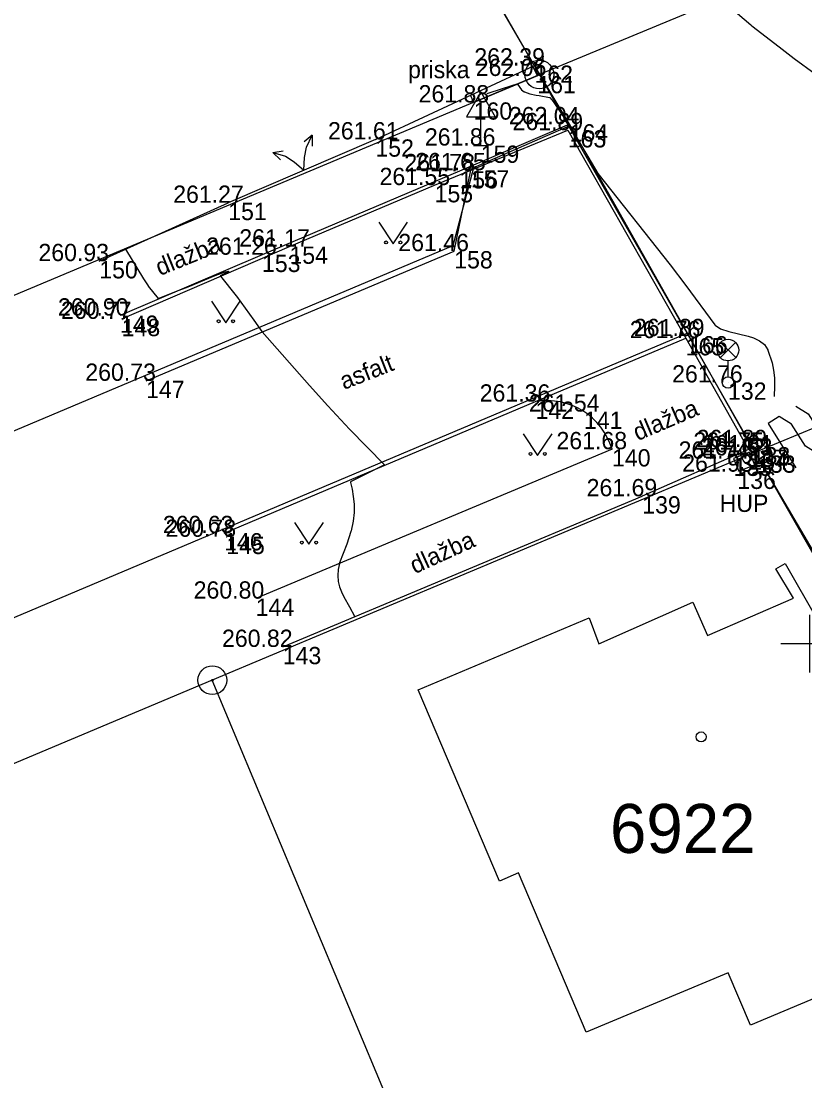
# Model space of a CAD drawing. Extents: x -771260 to -770828, y -1053564 to -1052811.
# Drawn here: x -771177.41 to -771150.16, y -1053315.19 to -1053278.38 of the extents above; entities that cross this region are included whole.
import ezdxf

# ---------------------------------------------------------------- set-up
doc = ezdxf.new("R2010")
doc.units = 0
for name, color, linetype in [('14_8_2023_krizky', 7, 'Continuous'), ('25_3_2019_dopravni_znacka', 7, 'Continuous'), ('25_3_2019_HUP', 7, 'Continuous'), ('25_3_2019_krizky_JTSK', 7, 'Continuous'), ('25_3_2019_lampa', 7, 'Continuous'), ('25_3_2019_obrubnik', 7, 'Continuous'), ('25_3_2019_oploceni', 7, 'Continuous'), ('25_3_2019_popis_objektu', 7, 'Continuous'), ('25_3_2019_popis_povrchu', 7, 'Continuous'), ('25_3_2019_priska', 7, 'Continuous'), ('25_3_2019_vrstevnice_interval_po_1m', 7, 'Continuous'), ('25_3_2019_vstup_vjezd_pozemek', 7, 'Continuous'), ('25_3_2019_zamereny_bod', 7, 'Continuous'), ('25_3_2019_zamereny_bod_cislo', 7, 'Continuous'), ('25_3_2019_zamereny_bod_vyska', 7, 'Continuous'), ('25_3_2019_znacka_zelen', 7, 'Continuous'), ('Default', 7, 'Continuous'), ('DKM_Hranice parcel', 7, 'Continuous'), ('DKM_Parcelní čísla', 7, 'Continuous'), ('DKM_Značky bodu BP', 7, 'Continuous'), ('DKM_Značky budov', 7, 'Continuous')]:
    doc.layers.add(name, color=color, linetype=linetype)

# ---------------------------------------------------------------- blocks, each defined once
blk = doc.blocks.new('Z58')
at = {"layer": '25_3_2019_vstup_vjezd_pozemek'}
for p, q in [((-7.5, 10), (-4, 7)), ((-7.5, 10), (-6, 6.51)), ((-7.5, 10), (-4, 9.01)), ((4, 7.01), (7.5, 10)), ((7.5, 10), (4, 9)), ((7.5, 10), (6, 6.5)), ((-4, 7), (-1.99, 4)), ((-1.99, 4), (0, 0)), ((0, 0), (2, 4)), ((2, 4), (4, 7.01))]:
    blk.add_line(p, q, dxfattribs=at)
blk = doc.blocks.new('5.270_1')
at = {"layer": '25_3_2019_dopravni_znacka'}
for p, q in [((0, 37.32), (-10, 20)), ((0, 37.32), (10, 20)), ((-10, 20), (10, 20)), ((0, 0), (0, 20)), ((-5, 0), (5, 0))]:
    blk.add_line(p, q, dxfattribs=at)
blk = doc.blocks.new('6.560_1')
at = {"layer": '25_3_2019_lampa'}
for p, q in [((-5.28, 17.24), (5.28, 27.8)), ((5.44, 17.3), (-5.12, 27.88)), ((0, 4), (0, 15))]:
    blk.add_line(p, q, dxfattribs=at)
for centre, radius in [((0, 22.5), 7.5), ((0, 0), 4), ((0, 0), 4)]:
    blk.add_circle(centre, radius, dxfattribs=at)
blk = doc.blocks.new('3.140_1')
at = {"layer": '25_3_2019_znacka_zelen'}
blk.add_lwpolyline([(-10, 15), (0, 0), (10, 15)], dxfattribs=at)
for centre in [(-5, 1), (-5, 1), (5, 1), (5, 1)]:
    blk.add_circle(centre, 1, dxfattribs=at)
blk = doc.blocks.new('POINT_DISPLAY')
at = {"layer": 'Default'}
blk.add_line((0, 0), (0, 0), dxfattribs=at)
blk = doc.blocks.new('KRIZEK')
at = {"layer": '25_3_2019_krizky_JTSK'}
for p, q in [((0, 10), (0, -10)), ((-10, 0), (10, 0))]:
    blk.add_line(p, q, dxfattribs=at)

msp = doc.modelspace()

# ---------------------------------------------------------------- linework, layer by layer
at = {"layer": '25_3_2019_HUP'}
for p, q in [((-771152.089, -1053293.353), (-771152.635, -1053293.573)), ((-771152.089, -1053293.353), (-771151.914, -1053293.786)), ((-771152.635, -1053293.573), (-771152.459, -1053294.007)), ((-771152.459, -1053294.007), (-771151.914, -1053293.786))]:
    msp.add_line(p, q, dxfattribs=at)
at = {"layer": '25_3_2019_obrubnik'}
for p, q in [((-771158.337, -1053281.957), (-771159.56, -1053279.916)), ((-771158.337, -1053281.957), (-771162.167, -1053283.587)), ((-771161.774, -1053283.553), (-771158.403, -1053282.162)), ((-771158.403, -1053282.162), (-771154.301, -1053289.385)), ((-771154.183, -1053289.316), (-771158.337, -1053281.957)), ((-771162.167, -1053283.587), (-771169.032, -1053286.491)), ((-771163.03, -1053284.07), (-771161.774, -1053283.553)), ((-771162.35, -1053286.365), (-771161.774, -1053283.553)), ((-771168.08, -1053286.204), (-771163.03, -1053284.07)), ((-771173.909, -1053288.719), (-771168.08, -1053286.204)), ((-771169.032, -1053286.491), (-771173.967, -1053288.602)), ((-771173.063, -1053290.868), (-771162.35, -1053286.365)), ((-771159.521, -1053291.591), (-771154.301, -1053289.385)), ((-771154.301, -1053289.385), (-771152.119, -1053293.257)), ((-771152.006, -1053293.172), (-771154.183, -1053289.316)), ((-771170.35, -1053296.16), (-771159.521, -1053291.591)), ((-771156.863, -1053293.244), (-771169.251, -1053298.435)), ((-771152.119, -1053293.257), (-771155.812, -1053294.879)), ((-771168.31, -1053300.113), (-771155.812, -1053294.879))]:
    msp.add_line(p, q, dxfattribs=at)
msp.add_arc((-771159.125, -1053293.917), 2.359, 16.5635, 99.6785, dxfattribs=at)
at = {"layer": '25_3_2019_oploceni'}
for p, q in [((-771159.56, -1053279.916), (-771167.412, -1053266.462)), ((-771165.09, -1053282.483), (-771159.56, -1053279.917)), ((-771174.69, -1053286.712), (-771170.207, -1053284.687)), ((-771147.237, -1053301.266), (-771151.821, -1053293.463))]:
    msp.add_line(p, q, dxfattribs=at)
at = {"layer": '25_3_2019_priska'}
for p, q in [((-771159.459, -1053280.28), (-771159.616, -1053279.943)), ((-771159.459, -1053280.28), (-771161.674, -1053281.197)), ((-771161.674, -1053281.197), (-771161.788, -1053280.951))]:
    msp.add_line(p, q, dxfattribs=at)
at = {"layer": '25_3_2019_vrstevnice_interval_po_1m'}
for points in [[(-771153.199, -1053277.504), (-771152.035, -1053278.507), (-771151.999, -1053278.538), (-771151.054, -1053279.264), (-771150.533, -1053279.674), (-771149.799, -1053280.202), (-771149.134, -1053280.696), (-771148.539, -1053281.114), (-771147.912, -1053281.584)], [(-771151.999, -1053278.538), (-771151.999, -1053278.538)], [(-771151.054, -1053279.264), (-771151.054, -1053279.264)], [(-771150.533, -1053279.674), (-771150.533, -1053279.674)], [(-771161.202, -1053280.893), (-771161.134, -1053280.871), (-771160.346, -1053280.607), (-771160.166, -1053280.554), (-771160.155, -1053280.569), (-771160.013, -1053280.764), (-771159.92, -1053280.831), (-771159.911, -1053280.835), (-771159.718, -1053280.901), (-771159.496, -1053280.946), (-771159.396, -1053280.957), (-771159.043, -1053281.023), (-771159.024, -1053281.027), (-771158.915, -1053281.164), (-771158.35, -1053281.99), (-771158.349, -1053281.992), (-771157.708, -1053283.073), (-771157.355, -1053283.669), (-771154.843, -1053286.846), (-771154.3, -1053287.553), (-771153.292, -1053288.928), (-771153.274, -1053288.94), (-771153.095, -1053289.064), (-771152.805, -1053289.16), (-771152.136, -1053289.318), (-771151.946, -1053289.378), (-771151.732, -1053289.475), (-771151.562, -1053289.608), (-771151.452, -1053289.79), (-771151.447, -1053289.803), (-771151.297, -1053290.247), (-771151.247, -1053290.498), (-771151.219, -1053290.767), (-771151.212, -1053291.052), (-771151.223, -1053291.412)], [(-771160.346, -1053280.607), (-771160.346, -1053280.607)], [(-771160.166, -1053280.554), (-771160.166, -1053280.554)], [(-771160.013, -1053280.764), (-771160.013, -1053280.764)], [(-771159.92, -1053280.831), (-771159.92, -1053280.831)], [(-771161.202, -1053280.893), (-771161.202, -1053280.893)], [(-771159.718, -1053280.901), (-771159.718, -1053280.901)], [(-771159.496, -1053280.946), (-771159.496, -1053280.946)], [(-771159.396, -1053280.957), (-771159.396, -1053280.957)], [(-771159.024, -1053281.027), (-771159.024, -1053281.027)], [(-771158.915, -1053281.164), (-771158.915, -1053281.164)], [(-771158.35, -1053281.99), (-771158.35, -1053281.99)], [(-771157.355, -1053283.669), (-771157.355, -1053283.669)], [(-771173.792, -1053286.287), (-771173.792, -1053286.287)], [(-771173.792, -1053286.287), (-771173.783, -1053286.302), (-771173.155, -1053287.329), (-771172.992, -1053287.569), (-771172.985, -1053287.578), (-771172.64, -1053288.015), (-771172.001, -1053287.761), (-771171.596, -1053287.6), (-771170.663, -1053287.216), (-771170.437, -1053287.132), (-771170.312, -1053287.086), (-771170.196, -1053287.063), (-771170.191, -1053287.071), (-771170.486, -1053287.223), (-771170.474, -1053287.237), (-771169.928, -1053287.918), (-771169.921, -1053287.928), (-771169.313, -1053288.759), (-771169.035, -1053289.156), (-771169.023, -1053289.17), (-771167.378, -1053291.032), (-771166.749, -1053291.734), (-771166.742, -1053291.742), (-771165.992, -1053292.546), (-771164.77, -1053293.786), (-771165.008, -1053293.906), (-771165.957, -1053294.383), (-771165.953, -1053294.401), (-771165.902, -1053294.629), (-771165.858, -1053294.884), (-771165.833, -1053295.153), (-771165.833, -1053295.44), (-771165.864, -1053295.749), (-771165.933, -1053296.083), (-771165.94, -1053296.107), (-771166.08, -1053296.539), (-771166.338, -1053297.196), (-771166.343, -1053297.218), (-771166.39, -1053297.425), (-771166.402, -1053297.637), (-771166.381, -1053297.835), (-771166.335, -1053298.023), (-771166.268, -1053298.202), (-771166.188, -1053298.375), (-771165.994, -1053298.723), (-771165.813, -1053299.048)], [(-771170.312, -1053287.086), (-771170.312, -1053287.086)], [(-771170.196, -1053287.063), (-771170.196, -1053287.063)], [(-771170.191, -1053287.071), (-771170.191, -1053287.071)], [(-771154.843, -1053286.846), (-771154.843, -1053286.846)], [(-771173.155, -1053287.329), (-771173.155, -1053287.329)], [(-771170.663, -1053287.216), (-771170.663, -1053287.216)], [(-771170.486, -1053287.223), (-771170.486, -1053287.223)], [(-771172.992, -1053287.569), (-771172.992, -1053287.569)], [(-771171.596, -1053287.6), (-771171.596, -1053287.6)], [(-771154.3, -1053287.553), (-771154.3, -1053287.553)], [(-771172.64, -1053288.015), (-771172.64, -1053288.015)], [(-771169.928, -1053287.918), (-771169.928, -1053287.918)], [(-771169.313, -1053288.759), (-771169.313, -1053288.759)], [(-771153.292, -1053288.928), (-771153.292, -1053288.928)], [(-771169.035, -1053289.156), (-771169.035, -1053289.156)], [(-771153.095, -1053289.064), (-771153.095, -1053289.064)], [(-771152.805, -1053289.16), (-771152.805, -1053289.16)], [(-771152.136, -1053289.318), (-771152.136, -1053289.318)], [(-771151.946, -1053289.378), (-771151.946, -1053289.378)], [(-771151.732, -1053289.475), (-771151.732, -1053289.475)], [(-771151.562, -1053289.608), (-771151.562, -1053289.608)], [(-771151.452, -1053289.79), (-771151.452, -1053289.79)], [(-771151.297, -1053290.247), (-771151.297, -1053290.247)], [(-771151.247, -1053290.498), (-771151.247, -1053290.498)], [(-771151.219, -1053290.767), (-771151.219, -1053290.767)], [(-771167.378, -1053291.032), (-771167.378, -1053291.032)], [(-771151.212, -1053291.052), (-771151.212, -1053291.052)], [(-771166.749, -1053291.734), (-771166.749, -1053291.734)], [(-771150.477, -1053291.749), (-771150.044, -1053292.013), (-771149.563, -1053292.783), (-771149.515, -1053293.288), (-771149.708, -1053293.408), (-771150.141, -1053293.144), (-771150.622, -1053292.374), (-771151.055, -1053292.109), (-771151.44, -1053292.35), (-771150.477, -1053293.89)], [(-771165.992, -1053292.546), (-771165.992, -1053292.546)], [(-771164.77, -1053293.786), (-771164.77, -1053293.786)], [(-771165.957, -1053294.383), (-771165.957, -1053294.383)], [(-771165.902, -1053294.629), (-771165.902, -1053294.629)], [(-771165.858, -1053294.884), (-771165.858, -1053294.884)], [(-771165.833, -1053295.153), (-771165.833, -1053295.153)], [(-771165.833, -1053295.44), (-771165.833, -1053295.44)], [(-771165.864, -1053295.749), (-771165.864, -1053295.749)], [(-771165.933, -1053296.083), (-771165.933, -1053296.083)], [(-771166.08, -1053296.539), (-771166.08, -1053296.539)], [(-771166.338, -1053297.196), (-771166.338, -1053297.196)], [(-771166.402, -1053297.637), (-771166.402, -1053297.637)], [(-771166.39, -1053297.425), (-771166.39, -1053297.425)], [(-771166.381, -1053297.835), (-771166.381, -1053297.835)], [(-771166.335, -1053298.023), (-771166.335, -1053298.023)], [(-771166.268, -1053298.202), (-771166.268, -1053298.202)], [(-771166.188, -1053298.375), (-771166.188, -1053298.375)], [(-771165.813, -1053299.048), (-771165.813, -1053299.048)], [(-771165.813, -1053299.048), (-771165.813, -1053299.048)]]:
    msp.add_lwpolyline(points, dxfattribs=at)
at = {"layer": '25_3_2019_vstup_vjezd_pozemek'}
msp.add_line((-771165.089, -1053282.482), (-771170.207, -1053284.687), dxfattribs=at)
at = {"layer": 'DKM_Hranice parcel'}
for p, q in [((-771159.39, -1053280.23), (-771161.21, -1053277.05)), ((-771182.78, -1053290.05), (-771159.39, -1053280.23)), ((-771158.36, -1053282.02), (-771159.39, -1053280.23)), ((-771154.25, -1053289.21), (-771158.36, -1053282.02)), ((-771151.89, -1053293.35), (-771154.25, -1053289.21)), ((-771151.89, -1053293.35), (-771170.76, -1053301.27)), ((-771170.76, -1053301.27), (-771191.78, -1053310.1)), ((-771157.67, -1053332.55), (-771170.76, -1053301.27))]:
    msp.add_line(p, q, dxfattribs=at)
for points in [[(-771114.64, -1053256.15), (-771110.79, -1053262.31), (-771110, -1053265.61), (-771121.4, -1053267.92), (-771131.13, -1053270.31), (-771140.72, -1053273.18), (-771150.13, -1053276.39), (-771159.39, -1053280.23)], [(-771158.36, -1053282.02), (-771161.68, -1053283.47), (-771162.4, -1053286.18), (-771217.48, -1053309.4), (-771221.52, -1053310.31), (-771225.4, -1053309.44), (-771229.05, -1053306.18), (-771230.58, -1053303.61), (-771236.43, -1053293.1), (-771247.022, -1053275.468)], [(-771151.89, -1053293.35), (-771144.83, -1053290.43), (-771136.15, -1053287.47), (-771127.19, -1053284.79), (-771125.28, -1053284.32)], [(-771052.58, -1053353.51), (-771052.72, -1053353.51), (-771055.78, -1053356.02), (-771073.82, -1053356.52), (-771091.31, -1053358.07), (-771113.44, -1053361.51), (-771130.6, -1053365.46), (-771143.48, -1053368.93), (-771156.62, -1053373.29), (-771169.24, -1053378.06), (-771181.81, -1053383.19), (-771186.16, -1053383.15), (-771190.19, -1053380.88), (-771192.42, -1053377.58), (-771218.46, -1053327.01), (-771219.54, -1053322.62), (-771219.14, -1053320.1), (-771217.59, -1053316.97), (-771214.46, -1053314.62), (-771154.25, -1053289.21)], [(-771134.86, -1053323.01), (-771144.3, -1053306.64), (-771151.89, -1053293.35)], [(-771154.06, -1053298.56), (-771153.54, -1053299.72), (-771150.56, -1053298.42), (-771151.17, -1053297.4), (-771150.85, -1053297.22), (-771144.15, -1053308.91), (-771144.47, -1053309.11), (-771146.17, -1053306.1), (-771149.32, -1053307.36), (-771147.63, -1053311.4), (-771152.05, -1053313.25), (-771152.83, -1053311.43), (-771157.76, -1053313.5), (-771160.11, -1053307.96), (-771160.78, -1053308.25), (-771163.6, -1053301.6), (-771157.66, -1053299.1), (-771157.32, -1053300.01), (-771154.06, -1053298.56)]]:
    msp.add_lwpolyline(points, dxfattribs=at)
at = {"layer": 'DKM_Značky bodu BP'}
for centre, radius in [((-771159.39, -1053280.23), 0.5), ((-771159.39, -1053280.23), 0.0303), ((-771151.89, -1053293.35), 0.5), ((-771151.89, -1053293.35), 0.0303), ((-771170.76, -1053301.27), 0.5), ((-771170.76, -1053301.27), 0.0303)]:
    msp.add_circle(centre, radius, dxfattribs=at)
at = {"layer": 'DKM_Značky budov'}
msp.add_circle((-771153.767, -1053303.239), 0.175, dxfattribs=at)

# ---------------------------------------------------------------- block references
at = {"layer": '14_8_2023_krizky', "xscale": 0.1, "yscale": 0.10000000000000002}
msp.add_blockref('KRIZEK', (-771150, -1053300), dxfattribs=at)
at = {"layer": '25_3_2019_dopravni_znacka', "xscale": 0.05, "yscale": 0.05000000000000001}
msp.add_blockref('5.270_1', (-771161.427, -1053282.697), dxfattribs=at)
at = {"layer": '25_3_2019_lampa', "xscale": 0.05, "yscale": 0.05000000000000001}
msp.add_blockref('6.560_1', (-771152.831, -1053290.927), dxfattribs=at)
at = {"layer": '25_3_2019_vstup_vjezd_pozemek', "xscale": 0.09999945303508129, "yscale": 0.09999945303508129, "rotation": 23.399927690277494}
msp.add_blockref('Z58', (-771167.576, -1053283.554), dxfattribs=at)
at = {"layer": '25_3_2019_zamereny_bod', "xscale": 0.1, "yscale": 0.10000000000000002}
for p in [(-771159.56, -1053279.917), (-771159.46, -1053280.281), (-771161.674, -1053281.198), (-771158.403, -1053282.163), (-771158.338, -1053281.957), (-771165.09, -1053282.483), (-771161.427, -1053282.697), (-771162.168, -1053283.588), (-771161.774, -1053283.553), (-771163.031, -1053284.07), (-771170.207, -1053284.687), (-771168.08, -1053286.205), (-771174.69, -1053286.712), (-771169.033, -1053286.491), (-771162.35, -1053286.365), (-771173.968, -1053288.602), (-771173.91, -1053288.719), (-771154.302, -1053289.386), (-771154.184, -1053289.317), (-771173.063, -1053290.869), (-771152.831, -1053290.927), (-771159.521, -1053291.591), (-771157.838, -1053291.939), (-771156.863, -1053293.245), (-771152.119, -1053293.258), (-771152.09, -1053293.353), (-771152.006, -1053293.172), (-771152.635, -1053293.574), (-771151.821, -1053293.463), (-771152.506, -1053294.026), (-771155.812, -1053294.88), (-771170.351, -1053296.16), (-771170.274, -1053296.289), (-771169.251, -1053298.436), (-771168.311, -1053300.113)]:
    msp.add_blockref('POINT_DISPLAY', p, dxfattribs=at)
at = {"layer": '25_3_2019_znacka_zelen', "xscale": 0.05, "yscale": 0.05000000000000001}
for p in [(-771164.47, -1053286.11), (-771170.29, -1053288.85), (-771159.45, -1053293.46), (-771167.4, -1053296.54)]:
    msp.add_blockref('3.140_1', p, dxfattribs=at)

# ---------------------------------------------------------------- texts
at = {"layer": '25_3_2019_popis_objektu'}
for s, p in [('priska', (-771163.955, -1053280.358)), ('HUP', (-771153.121, -1053295.424))]:
    msp.add_text(s, height=0.6, dxfattribs=at).set_placement(p)
at = {"layer": '25_3_2019_popis_povrchu'}
for s, rotation, p in [('dlažba', 21.8897, (-771172.586, -1053287.232)), ('asfalt', 21.4525, (-771166.183, -1053291.187)), ('dlažba', 23.097, (-771155.975, -1053292.967)), ('dlažba', 24.5471, (-771163.72, -1053297.588))]:
    msp.add_text(s, height=0.6, rotation=rotation, dxfattribs=at).set_placement(p)
at = {"layer": '25_3_2019_zamereny_bod_cislo'}
for s, p in [('162', (-771159.56, -1053280.517)), ('161', (-771159.46, -1053280.881)), ('160', (-771161.674, -1053281.798)), ('163', (-771158.403, -1053282.763)), ('164', (-771158.338, -1053282.557)), ('152', (-771165.09, -1053283.083)), ('159', (-771161.427, -1053283.297)), ('156', (-771162.168, -1053284.188)), ('157', (-771161.774, -1053284.153)), ('155', (-771163.031, -1053284.67)), ('151', (-771170.207, -1053285.287)), ('154', (-771168.08, -1053286.805)), ('158', (-771162.35, -1053286.965)), ('150', (-771174.69, -1053287.312)), ('153', (-771169.033, -1053287.091)), ('149', (-771173.968, -1053289.202)), ('148', (-771173.91, -1053289.319)), ('166', (-771154.184, -1053289.917)), ('165', (-771154.302, -1053289.986)), ('147', (-771173.063, -1053291.469)), ('132', (-771152.831, -1053291.527)), ('142', (-771159.521, -1053292.191)), ('141', (-771157.838, -1053292.539)), ('140', (-771156.863, -1053293.845)), ('137', (-771152.119, -1053293.858)), ('134', (-771152.09, -1053293.953)), ('138', (-771152.006, -1053293.772)), ('135', (-771152.635, -1053294.174)), ('133', (-771151.821, -1053294.063)), ('136', (-771152.506, -1053294.626)), ('139', (-771155.812, -1053295.48)), ('146', (-771170.351, -1053296.76)), ('145', (-771170.274, -1053296.889)), ('144', (-771169.251, -1053299.036)), ('143', (-771168.311, -1053300.713))]:
    msp.add_text(s, height=0.6, dxfattribs=at).set_placement(p)
at = {"layer": '25_3_2019_zamereny_bod_vyska'}
for s, p in [('262.39 ', (-771161.65, -1053279.917)), ('262.06 ', (-771161.6, -1053280.281)), ('261.88 ', (-771163.589, -1053281.198)), ('262.04 ', (-771160.45, -1053281.957)), ('261.89 ', (-771160.322, -1053282.163)), ('261.61 ', (-771166.738, -1053282.483)), ('261.86 ', (-771163.37, -1053282.697)), ('261.78 ', (-771164.083, -1053283.588)), ('261.65 ', (-771163.706, -1053283.553)), ('261.55 ', (-771164.946, -1053284.07)), ('261.27 ', (-771172.12, -1053284.687)), ('261.17 ', (-771169.822, -1053286.205)), ('261.26 ', (-771170.976, -1053286.491)), ('261.46 ', (-771164.293, -1053286.365)), ('260.93 ', (-771176.805, -1053286.712)), ('260.90 ', (-771176.128, -1053288.602)), ('260.77 ', (-771176.02, -1053288.719)), ('261.76 ', (-771156.245, -1053289.386)), ('261.89 ', (-771156.103, -1053289.317)), ('260.73 ', (-771175.175, -1053290.869)), ('261.76 ', (-771154.774, -1053290.927)), ('261.36 ', (-771161.464, -1053291.591)), ('261.54 ', (-771159.753, -1053291.939)), ('261.89 ', (-771153.925, -1053293.172)), ('261.68 ', (-771158.795, -1053293.245)), ('261.74 ', (-771154.55, -1053293.574)), ('261.75 ', (-771154.034, -1053293.258)), ('261.93 ', (-771153.739, -1053293.463)), ('261.81 ', (-771153.721, -1053293.353)), ('261.93 ', (-771154.424, -1053294.026)), ('261.69 ', (-771157.747, -1053294.88)), ('260.63 ', (-771172.48, -1053296.16)), ('260.78 ', (-771172.386, -1053296.289)), ('260.80 ', (-771171.409, -1053298.436)), ('260.82 ', (-771170.423, -1053300.113))]:
    msp.add_text(s, height=0.6, dxfattribs=at).set_placement(p)
at = {"layer": 'DKM_Parcelní čísla'}
msp.add_text('6922', height=1.7, dxfattribs=at).set_placement((-771156.934, -1053307.269))

doc.saveas('drawing.dxf')
